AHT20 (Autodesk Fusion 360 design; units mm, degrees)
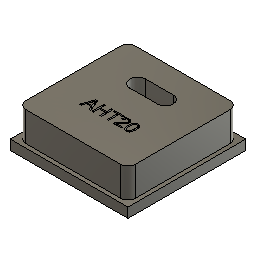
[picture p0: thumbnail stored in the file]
sketch "スケッチ1" plane through (0, 0, 0) normal (0, 1, 0) x axis (1, 0, 0)
  line L1 (3, 0) -> (0, 0)
  line L2 (3, -3) -> (3, 0)
  line L3 (0, -3) -> (3, -3)
  line L4 (0, 0) -> (0, -3)
  line L5 (0.5, 0) -> (0, 0)
  line L6 (0.5, -3) -> (0.5, 0)
  line L7 (0, -3) -> (0.5, -3)
  line L8 (0, 0) -> (0, -3)
  line L9 (2.5, 0) -> (3, 0)
  line L10 (2.5, -3) -> (2.5, 0)
  line L11 (3, -3) -> (2.5, -3)
  line L12 (3, 0) -> (3, -3)
  line L13 (3, 0) -> (0, 0)
  line L14 (3, -1.5) -> (3, 0)
  line L15 (0, -1.5) -> (3, -1.5)
  line L16 (0, 0) -> (0, -1.5)
  line L17 (3, -1.5) -> (0, -1.5)
  line L18 (3, -0.5) -> (3, -1.5)
  line L19 (0, -0.5) -> (3, -0.5)
  line L20 (0, -1.5) -> (0, -0.5)
  line L21 (3, -1.5) -> (0, -1.5)
  line L22 (3, -2.5) -> (3, -1.5)
  line L23 (0, -2.5) -> (3, -2.5)
  line L24 (0, -1.5) -> (0, -2.5)
  line L25 (0.225, -0.5) -> (0.5, -0.5)
  line L26 (0.225, -0.3) -> (0.225, -0.5)
  line L27 (0.5, -0.3) -> (0.225, -0.3)
  line L28 (0.5, -0.5) -> (0.5, -0.3)
  line L29 (0.775, -0.3) -> (0.225, -0.3)
  line L30 (0.775, -0.7) -> (0.775, -0.3)
  line L31 (0.225, -0.7) -> (0.775, -0.7)
  line L32 (0.225, -0.3) -> (0.225, -0.7)
  line L33 (0.775, -1.7) -> (0.775, -1.3)
  line L34 (0.225, -1.7) -> (0.775, -1.7)
  line L35 (0.775, -1.3) -> (0.225, -1.3)
  line L36 (0.225, -1.3) -> (0.225, -1.5)
  line L37 (0.225, -1.3) -> (0.225, -1.7)
  line L38 (2.775, -0.3) -> (2.225, -0.3)
  line L39 (2.225, -0.3) -> (2.225, -0.7)
  line L40 (2.225, -0.7) -> (2.775, -0.7)
  line L41 (2.775, -0.7) -> (2.775, -0.3)
  line L42 (2.775, -1.3) -> (2.225, -1.3)
  line L43 (2.225, -1.3) -> (2.225, -1.5)
  line L44 (2.225, -1.3) -> (2.225, -1.7)
  line L45 (2.225, -1.7) -> (2.775, -1.7)
  line L46 (2.775, -1.7) -> (2.775, -1.3)
  line L47 (0.775, -2.3) -> (0.225, -2.3)
  line L48 (0.225, -2.7) -> (0.775, -2.7)
  line L49 (0.225, -2.3) -> (0.225, -2.7)
  line L50 (0.775, -2.7) -> (0.775, -2.3)
  line L51 (2.225, -2.3) -> (2.225, -2.7)
  line L52 (2.775, -2.7) -> (2.775, -2.3)
  line L53 (2.775, -2.3) -> (2.225, -2.3)
  line L54 (2.225, -2.7) -> (2.775, -2.7)
  line L55 (0.1, -3) -> (0, -3)
  line L56 (0.1, -2.9) -> (0.1, -3)
  line L57 (0, -2.9) -> (0.1, -2.9)
  line L58 (0, -3) -> (0, -2.9)
  line L59 (2.9, -2.9) -> (0.1, -2.9)
  line L60 (2.9, -0.1) -> (2.9, -2.9)
  line L61 (0.1, -0.1) -> (2.9, -0.1)
  line L62 (0.1, -2.9) -> (0.1, -0.1)
  point P1 (0, 0)
  point P2 (0, 0)
  point P6 (0, 0)
  point P15 (3, -1.5)
  point P13 (0, 0)
  point P23 (0.5, -0.5)
  point P3 (3, 0)
  point P5 (0, -3)
  point P7 (0.5, 0)
  point P10 (2.5, 0)
  point P16 (0, -1.5)
  point P19 (0, -0.5)
  point P22 (0, -2.5)
  point P24 (0.225, -0.5)
  point P25 (0.225, -0.3)
  point P27 (0.775, -0.3)
  point P29 (0.225, -0.7)
  point P31 (0.225, -1.3)
  point P33 (0.775, -1.3)
  point P32 (0.225, -1.7)
  point P35 (2.225, -0.3)
  point P42 (2.775, -0.3)
  point P41 (2.225, -0.7)
  point P37 (2.225, -1.3)
  point P39 (2.775, -1.3)
  point P38 (2.225, -1.7)
  point P44 (0.225, -2.3)
  point P46 (0.775, -2.3)
  point P45 (0.225, -2.7)
  point P49 (2.775, -2.3)
  point P50 (2.225, -2.3)
  point P51 (2.225, -2.7)
  point P9 (0, -3)
  point P52 (0.1, -3)
  point P54 (0, -2.9)
  point P53 (0.1, -2.9)
  point P55 (2.9, -2.9)
  point P57 (0.1, -0.1)
  horizontal L1
  vertical L2
  horizontal L3
  vertical L4
  coincident P1 P2
  horizontal L5
  vertical L6
  horizontal L7
  vertical L8
  coincident P1 P6
  horizontal L9
  vertical L10
  horizontal L11
  vertical L12
  horizontal L13
  vertical L14
  horizontal L15
  vertical L16
  midpoint L12 P15
  coincident P1 P13
  horizontal L17
  vertical L18
  horizontal L19
  vertical L20
  horizontal L21
  vertical L22
  horizontal L23
  vertical L24
  horizontal L25
  vertical L26
  horizontal L27
  vertical L28
  coincident L6 P23
  coincident L19 P23
  horizontal L29
  vertical L30
  horizontal L31
  vertical L32
  vertical L36
  horizontal L35
  vertical L33
  horizontal L34
  vertical L37
  horizontal L38
  vertical L41
  horizontal L40
  vertical L39
  vertical L43
  horizontal L42
  vertical L46
  horizontal L45
  vertical L44
  horizontal L47
  vertical L50
  horizontal L48
  vertical L49
  horizontal L53
  vertical L52
  horizontal L54
  vertical L51
  horizontal L55
  vertical L56
  horizontal L57
  vertical L58
  horizontal L59
  vertical L60
  horizontal L61
  vertical L62
  dimension "d1" distance P2 P3 = 3
  dimension "d2" distance P2 P5 = 3
  dimension "d3" distance P6 P7 = 0.5
  dimension "d4" distance P3 P10 = 0.5
  dimension "d5" distance P13 P16 = 1.5
  dimension "d6" distance P16 P19 = 1
  dimension "d7" distance P16 P22 = 1
  dimension "d8" distance P23 P24 = 0.275 (= "( 0.55 / 2 ) * 1 mm")
  dimension "d9" distance P25 P27 = 0.55
  dimension "d10" distance P25 P29 = 0.4
  dimension "d11" distance P31 P33 = 0.55
  dimension "d12" distance P31 P32 = 0.4
  dimension "d13" distance P35 P42 = 0.55
  dimension "d14" distance P35 P41 = 0.4
  dimension "d15" distance P37 P39 = 0.55
  dimension "d16" distance P37 P38 = 0.4
  dimension "d17" distance P44 P46 = 0.55
  dimension "d18" distance P44 P45 = 0.4
  dimension "d19" distance P49 P50 = 0.55
  dimension "d20" distance P50 P51 = 0.4
  dimension "d23" distance P9 P52 = 0.1
  dimension "d24" distance P9 P54 = 0.1
  dimension "d25" distance P53 P55 = 2.8
  dimension "d26" distance P53 P57 = 2.8
extrude "押し出し2" new body sketch "スケッチ1" profile of L6 L10 L15 L17 L19 L21 L23 L25 L26 L27 L28 L29 L30 L31 L32 L33 L34 L35 L36 L37 L38 L39 L40 L41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 along normal blind 0.75
extrude "押し出し3" new body sketch "スケッチ1" profile of L1 L2 L3 L4 L5 L6 L7 L8 L9 L10 L11 L12 L13 L14 L15 L16 L17 L18 L19 L20 L21 L22 L23 L24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 against normal blind 0.25
extrude "押し出し4" new body sketch "スケッチ1" profile of L6 L10 L15 L17 L19 L21 L23 L25 L26 L27 L28 L29 L30 L31 L32 L33 L34 L35 L36 L37 L38 L39 L40 L41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 against normal blind 0.25
sketch "スケッチ2" plane through (0, 0.75, 0) normal (0, 1, 0) x axis (-1, 0, 0)
  line L1 (-0.1, 2.9) -> (-0.1, 0.1)
  line L2 (-2.9, 2.9) -> (-0.1, 2.9)
  line L3 (-2.9, 0.1) -> (-2.9, 2.9)
  line L4 (-0.1, 0.1) -> (-2.9, 0.1)
  line L5 (-0.95, 0.1) -> (-0.1, 0.1)
  line L6 (-0.95, 0.7) -> (-0.95, 0.1)
  line L7 (-0.1, 0.7) -> (-0.95, 0.7)
  line L8 (-0.1, 0.1) -> (-0.1, 0.7)
  line L9 (-2.05, 0.7) -> (-0.95, 0.7)
  line L10 (-2.05, 1.1) -> (-2.05, 0.7)
  line L11 (-0.95, 1.1) -> (-2.05, 1.1)
  line L12 (-0.95, 0.7) -> (-0.95, 1.1)
  line L13 (-1.15, 1.1) -> (-0.95, 1.1)
  line L14 (-1.15, 0.9) -> (-1.15, 1.1)
  line L15 (-0.95, 0.9) -> (-1.15, 0.9)
  line L16 (-0.95, 1.1) -> (-0.95, 0.9)
  line L17 (-1.85, 0.7) -> (-2.05, 0.7)
  line L18 (-1.85, 0.9) -> (-1.85, 0.7)
  line L19 (-2.05, 0.9) -> (-1.85, 0.9)
  line L20 (-2.05, 0.7) -> (-2.05, 0.9)
  curve K1
  curve K2
  curve K3
  curve K4
  arc A1 centre (-1.15, 0.9) radius 0.2 clockwise from (-1.15, 1.1) to (-1.15, 0.7)
  arc A2 centre (-1.85, 0.9) radius 0.2 clockwise from (-1.85, 0.7) to (-1.85, 1.1)
  point P2 (-0.1, 0.1)
  point P6 (-0.1, 0.1)
  point P17 (-1.15, 0.7)
  point P14 (-1.15, 0.9)
  point P16 (-1.15, 0.9)
  point P23 (-1.85, 1.1)
  point P20 (-1.85, 0.9)
  point P22 (-1.85, 0.9)
  point P7 (-0.95, 0.1)
  point P9 (-0.1, 0.7)
  point P8 (-0.95, 0.7)
  point P10 (-2.05, 0.7)
  point P12 (-0.95, 1.1)
  point P13 (-1.15, 1.1)
  point P15 (-0.95, 0.9)
  point P19 (-1.85, 0.7)
  point P21 (-2.05, 0.9)
  horizontal L5
  vertical L6
  horizontal L7
  vertical L8
  coincident P2 P6
  horizontal L9
  vertical L10
  horizontal L11
  vertical L12
  horizontal L13
  vertical L14
  horizontal L15
  vertical L16
  coincident L9 P17
  coincident P14 P16
  horizontal L17
  vertical L18
  horizontal L19
  vertical L20
  coincident L11 P23
  coincident P20 P22
  dimension "d33" distance P6 P7 = 0.85
  dimension "d34" distance P6 P9 = 0.6
  dimension "d35" distance P8 P10 = 1.1
  dimension "d36" distance P8 P12 = 0.4
  dimension "d37" distance P12 P13 = 0.2
  dimension "d38" distance P12 P15 = 0.2
  dimension "d39" distance P10 P19 = 0.2
  dimension "d40" distance P10 P21 = 0.2
  dimension "d51" Text1-Height = 0.3
extrude "押し出し5" cut sketch "スケッチ2" profile of L9 L11 L12 L14 L15 A1 L18 L19 A2 against normal blind 0.75
fillet "フィレット1" radius 0.2
fillet "フィレット2" radius 0.2
fillet "フィレット3" radius 0.2
fillet "フィレット4" radius 0.2
extrude "押し出し6" cut sketch "スケッチ2" against normal blind 0.1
